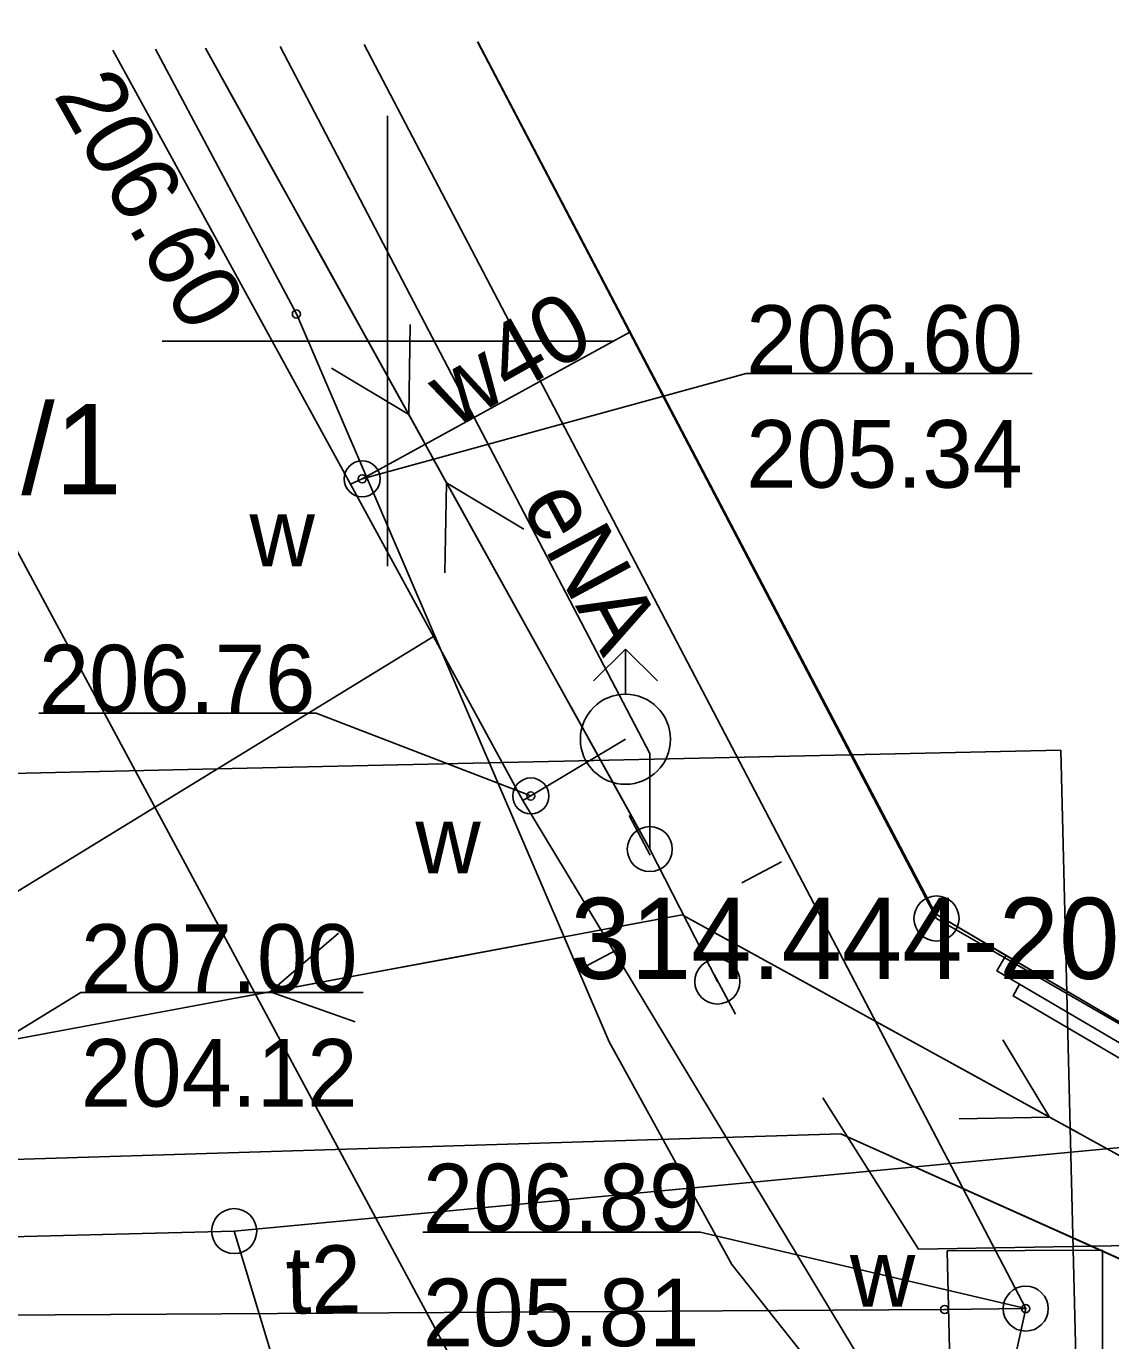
# Model space of a CAD drawing. Extents: x 6512606 to 6513347, y 6022524 to 6022728.
# Drawn here: x 6512795.99 to 6512808.02, y 6022688.9 to 6022703.49 of the extents above; entities that cross this region are included whole.
import ezdxf

# ---------------------------------------------------------------- set-up
doc = ezdxf.new("R2010")
doc.units = 0
for name, color, linetype in [('122-Punkt osnowy szczegółowej-Atr103', 7, 'Continuous'), ('202-punkt graniczny', 7, 'Continuous'), ('211-numer działki ewidencyjnej', 7, 'Continuous'), ('217-kontur klasyfikacyjny', 7, 'Continuous'), ('218-kontur użytku gruntowego', 7, 'Continuous'), ('219-działka ewidencyjna', 7, 'Continuous'), ('312-budynek ewidencyjny', 7, 'Continuous'), ('352-schody', 7, 'Continuous'), ('4', 7, 'Continuous'), ('chodnik (powierzchnia)', 7, 'Continuous'), ('Default', 7, 'Continuous'), ('hydrant (punkt)', 7, 'Continuous'), ('inna obudowa przewodu - sieć gazowa (linia)', 7, 'Continuous'), ('inna obudowa przewodu - sieć telekomunikacyjna (linia)', 7, 'Continuous'), ('komora podziemna - przewód telekomunikacyjny (powierzchnia)', 7, 'Continuous'), ('krawężnik (linia)', 7, 'Continuous'), ('latarnia na słupie lub maszcie (punkt)', 7, 'Continuous'), ('Obszar opracowania', 7, 'Continuous'), ('przewód elektroenergetyczny (linia)', 7, 'Continuous'), ('przewód elektroenergetyczny (linia)-Atr1', 7, 'Continuous'), ('przewód elektroenergetyczny niskiego napięcia (linia)', 7, 'Continuous'), ('przewód elektroenergetyczny niskiego napięcia (linia) - symbol', 7, 'Continuous'), ('przewód gazowy (linia)', 7, 'Continuous'), ('przewód kanalizacyjny (linia)', 7, 'Continuous'), ('przewód telekomunikacyjny (linia)', 7, 'Continuous'), ('przewód telekomunikacyjny (linia)-Atr1', 7, 'Continuous'), ('przewód wodociągowy (linia)', 7, 'Continuous'), ('przewód wodociągowy (linia)-Atr1', 7, 'Continuous'), ('punkt o określonej wysokości (sieć gazowa)-Atr2', 7, 'Continuous'), ('punkt o określonej wysokości (sieć gazowa)-Atr3', 7, 'Continuous'), ('punkt o określonej wysokości (sieć telekomunikacyjna)', 7, 'Continuous'), ('punkt o określonej wysokości (sieć telekomunikacyjna)-Atr2', 7, 'Continuous'), ('punkt o określonej wysokości (sieć telekomunikacyjna)-Atr3', 7, 'Continuous'), ('punkt o określonej wysokości (sieć wodociągowa)', 7, 'Continuous'), ('punkt o określonej wysokości (sieć wodociągowa)-Atr2', 7, 'Continuous'), ('punkt o określonej wysokości (sieć wodociągowa)-Atr3', 7, 'Continuous'), ('punkt wysokościowy sztuczny', 7, 'Continuous'), ('punkt wysokościowy sztuczny-Atr2', 7, 'Continuous'), ('słup łączony (linia)', 7, 'Continuous'), ('słup łączony (linia) - symbol', 7, 'Continuous'), ('właz okrągły - siec telekomunikacyjna (punkt)', 7, 'Continuous'), ('zasuwa - siec wodociągowa (punkt)', 7, 'Continuous'), ('zasuwa - siec wodociągowa (punkt)-Atr17', 7, 'Continuous')]:
    doc.layers.add(name, color=color, linetype=linetype)

# ---------------------------------------------------------------- blocks, each defined once
blk = doc.blocks.new('202')
at = {"layer": 'Default'}
blk.add_circle((0, 0), 2.5, dxfattribs=at)
blk = doc.blocks.new('PE04')
at = {"layer": 'Default'}
for p, q in [((46.5, 0), (37.84, 5)), ((6.5, 0), (0, 0)), ((6.5, 0), (16.5, 0)), ((16.5, 0), (26.5, 0)), ((26.5, 0), (36.5, 0)), ((36.5, 0), (46.5, 0)), ((46.5, 0), (37.84, -5)), ((46.5, 0), (50, 0))]:
    blk.add_line(p, q, dxfattribs=at)
blk = doc.blocks.new('PW01')
at = {"layer": 'Default'}
blk.add_circle((0, 0), 0.45, dxfattribs=at)
blk = doc.blocks.new('US22')
at = {"layer": 'Default'}
blk.add_circle((0, 0), 2.5, dxfattribs=at)
blk = doc.blocks.new('SM05')
at = {"layer": 'Default'}
blk.add_circle((0, 0), 2.5, dxfattribs=at)
blk = doc.blocks.new('SM011')
at = {"layer": 'Default'}
for p, q in [((-5.3, 5.31), (-8.83, 8.84)), ((5.31, 5.31), (8.84, 8.84)), ((-5.3, -5.3), (-8.83, -8.83)), ((5.31, -5.3), (8.84, -8.83))]:
    blk.add_line(p, q, dxfattribs=at)
blk = doc.blocks.new('US25')
at = {"layer": 'Default'}
blk.add_circle((0, 0), 2, dxfattribs=at)
blk = doc.blocks.new('US02')
at = {"layer": 'Default'}
for p, q in [((0, 10), (-3.53, 6.47)), ((0, 5), (0, 10)), ((0, 10), (3.54, 6.47))]:
    blk.add_line(p, q, dxfattribs=at)
blk.add_circle((0, 0), 5, dxfattribs=at)
blk = doc.blocks.new('PW02')
at = {"layer": 'Default'}
blk.add_circle((0, 0), 0.45, dxfattribs=at)

msp = doc.modelspace()

# ---------------------------------------------------------------- linework, layer by layer
at = {"layer": '217-kontur klasyfikacyjny'}
for points in [[(6512800.998, 6022703.319), (6512806.09, 6022693.59)], [(6512806.09, 6022693.59), (6512810.17, 6022691.24)]]:
    msp.add_lwpolyline(points, dxfattribs=at)
at = {"layer": '218-kontur użytku gruntowego'}
for points in [[(6512806.09, 6022693.59), (6512800.998, 6022703.319)], [(6512800.998, 6022703.319), (6512806.09, 6022693.59)], [(6512810.17, 6022691.24), (6512806.09, 6022693.59)], [(6512806.09, 6022693.59), (6512810.17, 6022691.24)], [(6512798.3, 6022690.12), (6512810.17, 6022691.24)], [(6512810.17, 6022691.24), (6512798.3, 6022690.12)], [(6512793.2, 6022689.99), (6512798.3, 6022690.12)], [(6512798.3, 6022690.12), (6512793.2, 6022689.99)], [(6512798.3, 6022690.12), (6512802.61, 6022675.86)], [(6512802.61, 6022675.86), (6512798.3, 6022690.12)]]:
    msp.add_lwpolyline(points, dxfattribs=at)
at = {"layer": '219-działka ewidencyjna'}
for points in [[(6512806.09, 6022693.59), (6512800.998, 6022703.319)], [(6512810.17, 6022691.24), (6512806.09, 6022693.59)], [(6512798.3, 6022690.12), (6512810.17, 6022691.24)], [(6512798.3, 6022690.12), (6512793.2, 6022689.99)], [(6512802.61, 6022675.86), (6512798.3, 6022690.12)]]:
    msp.add_lwpolyline(points, dxfattribs=at)
at = {"layer": '312-budynek ewidencyjny'}
for points in [[(6512806.08, 6022693.64), (6512801.001, 6022703.319)], [(6512810.11, 6022691.27), (6512806.08, 6022693.64)]]:
    msp.add_lwpolyline(points, dxfattribs=at)
at = {"layer": '352-schody'}
for p, q in [((6512806.86, 6022693.18), (6512806.76, 6022693.01)), ((6512809.32, 6022691.74), (6512806.86, 6022693.18)), ((6512806.76, 6022693.01), (6512807.01, 6022692.86)), ((6512807.01, 6022692.86), (6512806.94, 6022692.73)), ((6512807.01, 6022692.86), (6512809.04, 6022691.67)), ((6512806.94, 6022692.73), (6512808.97, 6022691.54))]:
    msp.add_line(p, q, dxfattribs=at)
at = {"layer": '4'}
for points in [[(6512806.09, 6022693.59), (6512800.998, 6022703.319)], [(6512810.17, 6022691.24), (6512806.09, 6022693.59)], [(6512798.3, 6022690.12), (6512810.17, 6022691.24)], [(6512798.3, 6022690.12), (6512793.2, 6022689.99)], [(6512802.61, 6022675.86), (6512798.3, 6022690.12)]]:
    msp.add_lwpolyline(points, dxfattribs=at)
at = {"layer": 'chodnik (powierzchnia)'}
msp.add_lwpolyline([(6512810.11, 6022691.27), (6512809.32, 6022691.74), (6512809.22, 6022691.57), (6512809.04, 6022691.67), (6512808.97, 6022691.54), (6512806.94, 6022692.73), (6512807.01, 6022692.86), (6512806.76, 6022693.01), (6512806.86, 6022693.18), (6512806.08, 6022693.64), (6512801.003, 6022703.319)], dxfattribs=at)
at = {"layer": 'Default'}
for p, q in [((6512800, 6022697.5), (6512800, 6022702.5)), ((6512800, 6022697.5), (6512800, 6022702.5)), ((6512797.5, 6022700), (6512800, 6022700)), ((6512800, 6022700), (6512802.5, 6022700))]:
    msp.add_line(p, q, dxfattribs=at)
at = {"layer": 'inna obudowa przewodu - sieć gazowa (linia)'}
msp.add_lwpolyline([(6512808.9, 6022689.46), (6512805.03, 6022691.2), (6512793.46, 6022690.84)], dxfattribs=at)
at = {"layer": 'inna obudowa przewodu - sieć telekomunikacyjna (linia)'}
msp.add_lwpolyline([(6512794.41, 6022689.18), (6512794.46, 6022689.18), (6512806.18, 6022689.25), (6512806.23, 6022689.25)], dxfattribs=at)
at = {"layer": 'komora podziemna - przewód telekomunikacyjny (powierzchnia)'}
msp.add_lwpolyline([(6512806.24, 6022688.65), (6512806.21, 6022689.9), (6512807.93, 6022689.91), (6512807.93, 6022688.66)], close=True, dxfattribs=at)
at = {"layer": 'krawężnik (linia)'}
msp.add_lwpolyline([(6512810.65, 6022686.18), (6512808.52, 6022686.51), (6512806.36, 6022687.33), (6512804.86, 6022688.44), (6512803.82, 6022689.75), (6512802.46, 6022692.22), (6512798.99, 6022700.3), (6512797.428, 6022703.239)], dxfattribs=at)
at = {"layer": 'Obszar opracowania'}
msp.add_lwpolyline([(6512710.98, 6022693.84), (6512748.35, 6022694.16), (6512798.11, 6022695.25), (6512807.47, 6022695.46), (6512809.66, 6022606.87), (6512863.71, 6022622.03), (6512875.13, 6022581.36), (6512755.22, 6022535.25), (6512691.61, 6022568.03), (6512709.16, 6022605.16)], close=True, dxfattribs=at)
at = {"layer": 'przewód elektroenergetyczny (linia)'}
for points in [[(6512798.809, 6022703.27), (6512802.91, 6022695.42), (6512802.91, 6022694.36)], [(6512804.83, 6022691.6), (6512805.89, 6022689.92), (6512810.59, 6022690), (6512816.98, 6022689.19), (6512818.13, 6022690.17), (6512819.01, 6022690.24), (6512819.69, 6022689.7), (6512825.585, 6022689.929)]]:
    msp.add_lwpolyline(points, dxfattribs=at)
at = {"layer": 'przewód elektroenergetyczny niskiego napięcia (linia)'}
for points in [[(6512802.91, 6022694.36), (6512797.982, 6022703.251)], [(6512803.27, 6022693.63), (6512782.09, 6022689.68)], [(6512814.78, 6022687.29), (6512803.27, 6022693.63)]]:
    msp.add_lwpolyline(points, dxfattribs=at)
at = {"layer": 'przewód gazowy (linia)'}
msp.add_lwpolyline([(6512808.91, 6022689.46), (6512805.03, 6022691.2), (6512793.46, 6022690.84)], dxfattribs=at)
at = {"layer": 'przewód kanalizacyjny (linia)'}
msp.add_lwpolyline([(6512803.88, 6022681.97), (6512803.01, 6022684.42), (6512792.949, 6022703.141)], dxfattribs=at)
at = {"layer": 'przewód telekomunikacyjny (linia)'}
for points in [[(6512799.742, 6022703.291), (6512807.08, 6022689.26)], [(6512793.56, 6022689.17), (6512794.46, 6022689.18), (6512806.18, 6022689.25), (6512807.08, 6022689.26)], [(6512803.2, 6022671.69), (6512803.36, 6022672.42), (6512806.94, 6022688.62), (6512807.08, 6022689.26)]]:
    msp.add_lwpolyline(points, dxfattribs=at)
at = {"layer": 'przewód wodociągowy (linia)'}
for points in [[(6512805.45, 6022688.13), (6512805.41, 6022688.42), (6512801.5, 6022694.9), (6512799.59, 6022698.41), (6512796.954, 6022703.229)], [(6512802.69, 6022700.1), (6512799.72, 6022698.47), (6512799.59, 6022698.41)], [(6512800.51, 6022696.72), (6512794.8, 6022693.22)], [(6512801.5, 6022694.9), (6512801.59, 6022694.95), (6512802.64, 6022695.58)]]:
    msp.add_lwpolyline(points, dxfattribs=at)
at = {"layer": 'punkt o określonej wysokości (sieć gazowa)-Atr2'}
msp.add_lwpolyline([(6512793.46, 6022690.84), (6512796.6, 6022692.77), (6512799.73, 6022692.77)], dxfattribs=at)
at = {"layer": 'punkt o określonej wysokości (sieć telekomunikacyjna)-Atr2'}
msp.add_lwpolyline([(6512807.08, 6022689.26), (6512803.47, 6022690.11), (6512800.393, 6022690.11)], dxfattribs=at)
at = {"layer": 'punkt o określonej wysokości (sieć wodociągowa)-Atr2'}
for points in [[(6512799.72, 6022698.47), (6512803.98, 6022699.64), (6512807.153, 6022699.64)], [(6512801.59, 6022694.95), (6512799.21, 6022695.87), (6512796.133, 6022695.87)]]:
    msp.add_lwpolyline(points, dxfattribs=at)
at = {"layer": 'słup łączony (linia)'}
msp.add_lwpolyline([(6512802.91, 6022694.36), (6512803.66, 6022692.89)], dxfattribs=at)

# ---------------------------------------------------------------- block references
at = {"layer": '202-punkt graniczny', "xscale": 0.1, "yscale": 0.10000000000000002}
for p in [(6512806.09, 6022693.59), (6512798.3, 6022690.12)]:
    msp.add_blockref('202', p, dxfattribs=at)
at = {"layer": 'hydrant (punkt)', "xscale": 0.1, "yscale": 0.10000000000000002}
msp.add_blockref('US02', (6512802.64, 6022695.58), dxfattribs=at)
at = {"layer": 'latarnia na słupie lub maszcie (punkt)', "xscale": 0.1, "yscale": 0.10000000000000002, "rotation": 73.171}
msp.add_blockref('SM011', (6512803.27, 6022693.63), dxfattribs=at)
at = {"layer": 'przewód elektroenergetyczny niskiego napięcia (linia) - symbol'}
for p, xscale, yscale, rotation in [((6512797.982, 6022703.251), 0.09999999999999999, 0.09999999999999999, -61.002), ((6512802.91, 6022694.36), 0.1, 0.09999999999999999, 118.998), ((6512803.27, 6022693.63), 0.10000000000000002, 0.09999999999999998, -169.43600000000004), ((6512803.27, 6022693.63), 0.09999999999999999, 0.10000000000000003, -28.846999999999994)]:
    msp.add_blockref('PE04', p, dxfattribs=dict(at, xscale=xscale, yscale=yscale, rotation=rotation))
at = {"layer": 'punkt o określonej wysokości (sieć telekomunikacyjna)', "xscale": 0.10000000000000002, "yscale": 0.10000000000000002, "rotation": 1.187}
msp.add_blockref('PW01', (6512806.18, 6022689.25), dxfattribs=at)
at = {"layer": 'punkt o określonej wysokości (sieć telekomunikacyjna)', "xscale": 0.1, "yscale": 0.10000000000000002}
msp.add_blockref('PW01', (6512807.08, 6022689.26), dxfattribs=at)
at = {"layer": 'punkt o określonej wysokości (sieć wodociągowa)', "xscale": 0.1, "yscale": 0.09999999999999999}
for p, rotation in [((6512799.72, 6022698.47), 29.514), ((6512801.59, 6022694.95), 29.055000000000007)]:
    msp.add_blockref('PW01', p, dxfattribs=dict(at, rotation=rotation))
at = {"layer": 'punkt wysokościowy sztuczny', "xscale": 0.1, "yscale": 0.10000000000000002}
msp.add_blockref('PW02', (6512798.99, 6022700.3), dxfattribs=at)
at = {"layer": 'słup łączony (linia) - symbol', "xscale": 0.1, "yscale": 0.10000000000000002}
for p in [(6512802.91, 6022694.36), (6512803.66, 6022692.89)]:
    msp.add_blockref('SM05', p, dxfattribs=at)
at = {"layer": 'właz okrągły - siec telekomunikacyjna (punkt)', "xscale": 0.1, "yscale": 0.10000000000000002}
msp.add_blockref('US22', (6512807.08, 6022689.26), dxfattribs=at)
at = {"layer": 'zasuwa - siec wodociągowa (punkt)', "xscale": 0.1, "yscale": 0.09999999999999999}
for p, rotation in [((6512799.72, 6022698.47), 29.514), ((6512801.59, 6022694.95), 29.055000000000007)]:
    msp.add_blockref('US25', p, dxfattribs=dict(at, rotation=rotation))

# ---------------------------------------------------------------- texts
at = {"layer": '122-Punkt osnowy szczegółowej-Atr103'}
msp.add_text('314.444-2003', height=0.9, dxfattribs=at).set_placement((6512802.03, 6022692.92))
at = {"layer": '211-numer działki ewidencyjnej'}
msp.add_text('58/1', height=1, dxfattribs=at).set_placement((6512794.45, 6022698.3))
at = {"layer": '4'}
msp.add_text('58/1', height=1, dxfattribs=at).set_placement((6512794.45, 6022698.3))
at = {"layer": 'przewód elektroenergetyczny (linia)-Atr1'}
msp.add_text('eNA', height=0.75, rotation=298.355, dxfattribs=at).set_placement((6512801.47, 6022698.19))
at = {"layer": 'przewód telekomunikacyjny (linia)-Atr1'}
msp.add_text('t2', height=0.75, rotation=1.187, dxfattribs=at).set_placement((6512798.88, 6022689.2))
at = {"layer": 'przewód wodociągowy (linia)-Atr1'}
msp.add_text('w40', height=0.75, rotation=29.488, dxfattribs=at).set_placement((6512800.73, 6022699.03))
at = {"layer": 'punkt o określonej wysokości (sieć gazowa)-Atr2'}
msp.add_text('207.00', height=0.75, dxfattribs=at).set_placement((6512796.6, 6022692.777))
at = {"layer": 'punkt o określonej wysokości (sieć gazowa)-Atr3'}
msp.add_text('204.12', height=0.75, dxfattribs=at).set_placement((6512796.6, 6022691.502))
at = {"layer": 'punkt o określonej wysokości (sieć telekomunikacyjna)-Atr2'}
msp.add_text('206.89', height=0.75, dxfattribs=at).set_placement((6512800.393, 6022690.118))
at = {"layer": 'punkt o określonej wysokości (sieć telekomunikacyjna)-Atr3'}
msp.add_text('205.81', height=0.75, dxfattribs=at).set_placement((6512800.393, 6022688.843))
at = {"layer": 'punkt o określonej wysokości (sieć wodociągowa)-Atr2'}
for s, p in [('206.60', (6512803.98, 6022699.647)), ('206.76', (6512796.133, 6022695.878))]:
    msp.add_text(s, height=0.75, dxfattribs=at).set_placement(p)
at = {"layer": 'punkt o określonej wysokości (sieć wodociągowa)-Atr3'}
msp.add_text('205.34', height=0.75, dxfattribs=at).set_placement((6512803.98, 6022698.372))
at = {"layer": 'punkt wysokościowy sztuczny-Atr2'}
msp.add_text('206.60', height=0.75, rotation=299.452, dxfattribs=at).set_placement((6512796.29, 6022702.73))
at = {"layer": 'zasuwa - siec wodociągowa (punkt)-Atr17'}
for p in [(6512798.47, 6022697.5), (6512800.31, 6022694.09), (6512805.13, 6022689.28)]:
    msp.add_text('w', height=0.75, dxfattribs=at).set_placement(p)

doc.saveas('drawing.dxf')
